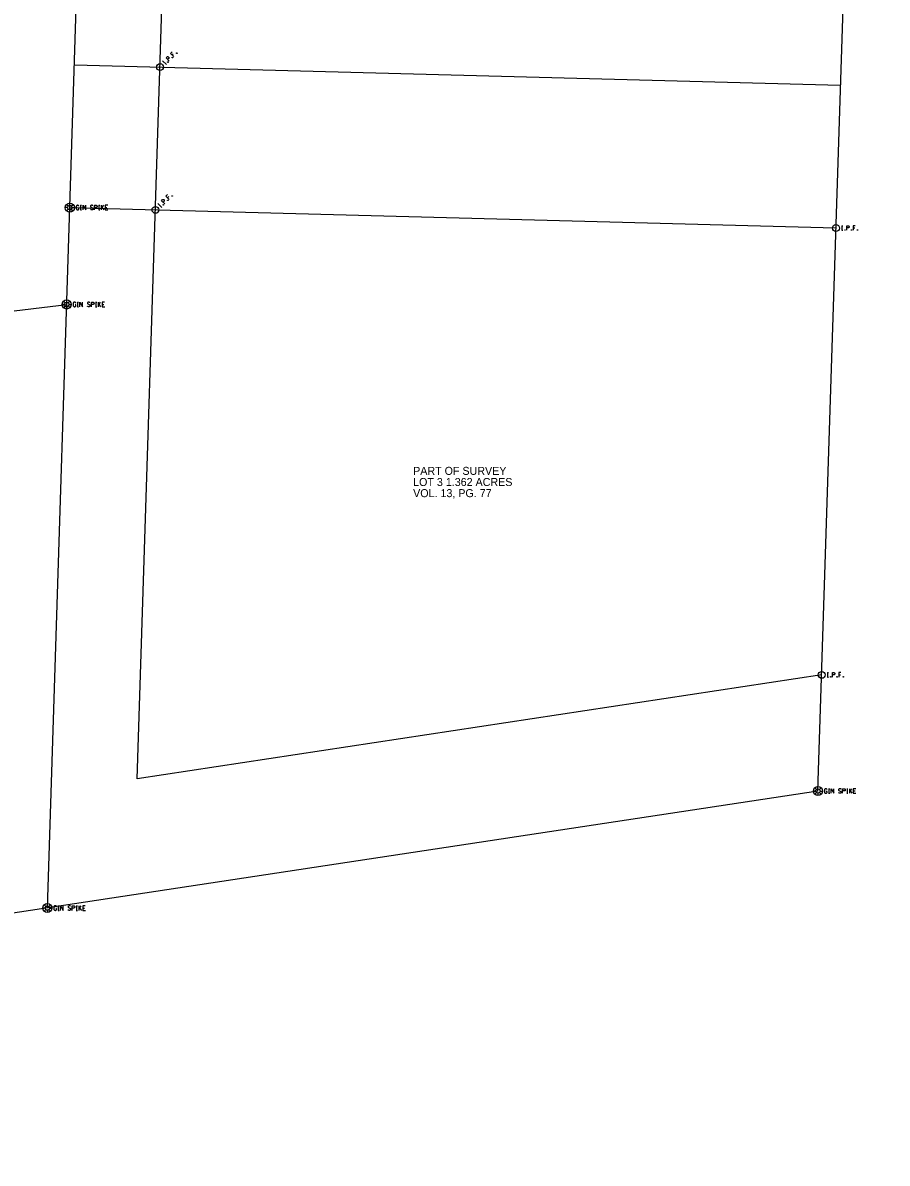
# Model space of a CAD drawing. Extents: x 1532954 to 1577849, y 698998 to 706606.
# Drawn here: x 1534496 to 1534798.6, y 703091.1 to 703490.2 of the extents above; entities that cross this region are included whole.
import ezdxf

# ---------------------------------------------------------------- set-up
doc = ezdxf.new("R2010")
doc.units = 0
doc.layers.add('SC_Scratch3', color=7, linetype='Continuous')

msp = doc.modelspace()

# ---------------------------------------------------------------- linework, layer by layer
at = {"layer": 'SC_Scratch3'}
for p, q in [((1534774.37, 703221.39), (1534798.62, 703978.77)), ((1534504.63, 703180.43), (1534518.99, 703629.17)), ((1534536.09, 703225.67), (1534548.98, 703628.3)), ((1534514.07, 703475.55), (1534782.28, 703468.41)), ((1534511.72, 703425.57), (1534510.87, 703425.57)), ((1534511.94, 703426.1), (1534511.34, 703426.71)), ((1534511.94, 703425.04), (1534511.34, 703424.44)), ((1534512.47, 703426.32), (1534512.47, 703427.17)), ((1534512.47, 703425.57), (1534780.69, 703418.44)), ((1534512.47, 703424.82), (1534512.47, 703423.97)), ((1534513, 703426.1), (1534513.61, 703426.71)), ((1534513, 703425.04), (1534513.61, 703424.44)), ((1534513.22, 703425.57), (1534514.07, 703425.57)), ((1534142.49, 703347.63), (1534511.39, 703391.68)), ((1534510.64, 703391.68), (1534509.79, 703391.68)), ((1534510.86, 703392.21), (1534510.26, 703392.81)), ((1534511.39, 703392.43), (1534511.39, 703393.28)), ((1534511.92, 703392.21), (1534512.52, 703392.81)), ((1534512.14, 703391.68), (1534512.99, 703391.68)), ((1534510.86, 703391.15), (1534510.26, 703390.55)), ((1534511.39, 703390.93), (1534511.39, 703390.08)), ((1534511.92, 703391.15), (1534512.52, 703390.55)), ((1534775.68, 703262.05), (1534536.09, 703225.67)), ((1534774.37, 703221.39), (1533916.61, 703091.14)), ((1534773.62, 703221.39), (1534772.77, 703221.39)), ((1534773.84, 703221.92), (1534773.24, 703222.52)), ((1534773.84, 703220.86), (1534773.24, 703220.26)), ((1534774.37, 703222.14), (1534774.37, 703222.99)), ((1534774.37, 703220.64), (1534774.37, 703219.79)), ((1534774.91, 703221.92), (1534775.51, 703222.52)), ((1534774.91, 703220.86), (1534775.51, 703220.26)), ((1534775.12, 703221.39), (1534775.97, 703221.39)), ((1534503.88, 703180.43), (1534503.03, 703180.43)), ((1534504.1, 703180.96), (1534503.5, 703181.56)), ((1534504.63, 703181.18), (1534504.63, 703182.03)), ((1534505.16, 703180.96), (1534505.76, 703181.56)), ((1534505.38, 703180.43), (1534506.23, 703180.43)), ((1534504.1, 703179.9), (1534503.5, 703179.3)), ((1534504.63, 703179.68), (1534504.63, 703178.83)), ((1534505.16, 703179.9), (1534505.76, 703179.3))]:
    msp.add_line(p, q, dxfattribs=at)
for points in [[(1534548.28, 703480.1), (1534547.74, 703479.56), (1534548.87, 703478.43)], [(1534549.81, 703479.67), (1534549.85, 703479.71), (1534549.89, 703479.72), (1534549.95, 703479.71), (1534550, 703479.66), (1534550.01, 703479.6), (1534550, 703479.56), (1534549.97, 703479.52), (1534549.92, 703479.52), (1534549.87, 703479.53), (1534549.82, 703479.57), (1534549.81, 703479.63), (1534549.81, 703479.67)], [(1534544.92, 703476.74), (1534545.17, 703476.99)], [(1534546.18, 703475.73), (1534545.05, 703476.87)], [(1534546.05, 703475.61), (1534546.3, 703475.86)], [(1534547.28, 703476.84), (1534546.15, 703477.97), (1534546.53, 703478.35), (1534546.58, 703478.38), (1534546.65, 703478.41), (1534546.69, 703478.42), (1534546.73, 703478.42), (1534546.81, 703478.41), (1534546.87, 703478.39), (1534546.96, 703478.33), (1534547.07, 703478.23), (1534547.1, 703478.18), (1534547.13, 703478.11), (1534547.16, 703478.02), (1534547.16, 703477.96), (1534547.15, 703477.92), (1534547.13, 703477.87), (1534547.08, 703477.79), (1534546.71, 703477.42)], [(1534546.7, 703476.56), (1534546.74, 703476.6), (1534546.78, 703476.61), (1534546.84, 703476.6), (1534546.89, 703476.55), (1534546.9, 703476.49), (1534546.9, 703476.45), (1534546.86, 703476.41), (1534546.81, 703476.41), (1534546.76, 703476.42), (1534546.71, 703476.46), (1534546.7, 703476.52), (1534546.7, 703476.56)], [(1534548.29, 703478.15), (1534548.33, 703478.19), (1534548.37, 703478.2), (1534548.43, 703478.19), (1534548.48, 703478.14), (1534548.49, 703478.08), (1534548.49, 703478.04), (1534548.45, 703478), (1534548.4, 703478), (1534548.35, 703478.01), (1534548.3, 703478.05), (1534548.29, 703478.11), (1534548.29, 703478.15)], [(1534548.3, 703479.01), (1534548.68, 703479.39)], [(1534545.69, 703426.87), (1534544.55, 703428), (1534544.93, 703428.37), (1534544.98, 703428.4), (1534545.05, 703428.44), (1534545.09, 703428.44), (1534545.13, 703428.45), (1534545.21, 703428.44), (1534545.27, 703428.41), (1534545.36, 703428.36), (1534545.47, 703428.25), (1534545.5, 703428.21), (1534545.53, 703428.14), (1534545.56, 703428.05), (1534545.56, 703427.99), (1534545.55, 703427.95), (1534545.53, 703427.89), (1534545.48, 703427.82), (1534545.11, 703427.45)], [(1534546.68, 703430.13), (1534546.14, 703429.59), (1534547.28, 703428.46)], [(1534546.7, 703428.18), (1534546.73, 703428.22), (1534546.78, 703428.22), (1534546.83, 703428.21), (1534546.88, 703428.17), (1534546.89, 703428.11), (1534546.89, 703428.07), (1534546.85, 703428.03), (1534546.81, 703428.02), (1534546.75, 703428.03), (1534546.7, 703428.08), (1534546.69, 703428.14), (1534546.7, 703428.18)], [(1534546.7, 703429.04), (1534547.08, 703429.42)], [(1534548.21, 703429.7), (1534548.25, 703429.74), (1534548.3, 703429.74), (1534548.35, 703429.73), (1534548.4, 703429.69), (1534548.41, 703429.63), (1534548.41, 703429.59), (1534548.37, 703429.55), (1534548.33, 703429.54), (1534548.27, 703429.55), (1534548.22, 703429.6), (1534548.21, 703429.66), (1534548.21, 703429.7)], [(1534515.66, 703426.06), (1534515.65, 703426.12), (1534515.61, 703426.18), (1534515.55, 703426.25), (1534515.46, 703426.32), (1534515.4, 703426.35), (1534515.35, 703426.36), (1534515.27, 703426.37), (1534515.12, 703426.37), (1534515.06, 703426.36), (1534515.02, 703426.35), (1534514.97, 703426.32), (1534514.87, 703426.25), (1534514.8, 703426.16), (1534514.77, 703426.06), (1534514.74, 703425.92), (1534514.72, 703425.72), (1534514.72, 703425.45), (1534514.73, 703425.24), (1534514.78, 703425.08), (1534514.86, 703424.92), (1534514.92, 703424.87), (1534514.99, 703424.82), (1534515.13, 703424.77), (1534515.27, 703424.77), (1534515.41, 703424.8), (1534515.46, 703424.82), (1534515.51, 703424.85), (1534515.56, 703424.9), (1534515.61, 703424.98), (1534515.66, 703425.09), (1534515.66, 703425.4), (1534515.4, 703425.4)], [(1534516.19, 703426.37), (1534516.59, 703426.37)], [(1534516.19, 703424.77), (1534516.59, 703424.77)], [(1534516.39, 703424.77), (1534516.39, 703426.37)], [(1534517.1, 703424.77), (1534517.1, 703426.37), (1534518.04, 703424.77), (1534518.04, 703426.37)], [(1534520.56, 703426.26), (1534520.54, 703426.29), (1534520.5, 703426.31), (1534520.39, 703426.35), (1534520.25, 703426.37), (1534520.15, 703426.37), (1534520.11, 703426.37), (1534519.94, 703426.34), (1534519.81, 703426.26), (1534519.72, 703426.16), (1534519.69, 703426.06), (1534519.69, 703425.98), (1534519.72, 703425.88), (1534519.82, 703425.79), (1534520.51, 703425.42), (1534520.57, 703425.37), (1534520.6, 703425.32), (1534520.62, 703425.24), (1534520.62, 703425.16), (1534520.61, 703425.09), (1534520.6, 703425.04), (1534520.57, 703424.98), (1534520.55, 703424.92), (1534520.52, 703424.89), (1534520.49, 703424.85), (1534520.45, 703424.82), (1534520.4, 703424.8), (1534520.36, 703424.79), (1534520.25, 703424.77), (1534520.07, 703424.77), (1534519.96, 703424.8), (1534519.79, 703424.89), (1534519.69, 703424.96)], [(1534521.1, 703424.77), (1534521.1, 703426.37), (1534521.71, 703426.37), (1534521.77, 703426.36), (1534521.86, 703426.34), (1534521.9, 703426.31), (1534521.93, 703426.29), (1534521.99, 703426.22), (1534522.02, 703426.16), (1534522.05, 703426.06), (1534522.05, 703425.91), (1534522.04, 703425.86), (1534522.01, 703425.78), (1534521.96, 703425.69), (1534521.91, 703425.66), (1534521.87, 703425.63), (1534521.81, 703425.61), (1534521.71, 703425.59), (1534521.1, 703425.59)], [(1534522.59, 703426.37), (1534522.99, 703426.37)], [(1534522.59, 703424.77), (1534522.99, 703424.77)], [(1534522.79, 703424.77), (1534522.79, 703426.37)], [(1534523.5, 703426.37), (1534523.5, 703424.77)], [(1534524.23, 703426.37), (1534523.5, 703425.35)], [(1534523.74, 703425.68), (1534524.35, 703424.77)], [(1534525.73, 703426.37), (1534524.86, 703426.37), (1534524.86, 703424.77), (1534525.79, 703424.77)], [(1534524.86, 703425.58), (1534525.47, 703425.58)], [(1534543.32, 703426.77), (1534543.57, 703427.02)], [(1534544.58, 703425.76), (1534543.45, 703426.89)], [(1534544.45, 703425.63), (1534544.7, 703425.88)], [(1534545.11, 703426.59), (1534545.14, 703426.63), (1534545.19, 703426.63), (1534545.24, 703426.62), (1534545.29, 703426.58), (1534545.3, 703426.52), (1534545.3, 703426.48), (1534545.26, 703426.44), (1534545.22, 703426.43), (1534545.16, 703426.44), (1534545.11, 703426.49), (1534545.1, 703426.55), (1534545.11, 703426.59)], [(1534782.7, 703419.23), (1534783.05, 703419.23)], [(1534782.7, 703417.63), (1534783.05, 703417.63)], [(1534782.87, 703417.63), (1534782.87, 703419.23)], [(1534783.83, 703417.84), (1534783.89, 703417.84), (1534783.92, 703417.82), (1534783.95, 703417.77), (1534783.95, 703417.71), (1534783.92, 703417.66), (1534783.89, 703417.63), (1534783.83, 703417.63), (1534783.8, 703417.66), (1534783.77, 703417.71), (1534783.77, 703417.77), (1534783.8, 703417.82), (1534783.83, 703417.84)], [(1534784.44, 703417.63), (1534784.44, 703419.23), (1534784.97, 703419.23), (1534785.02, 703419.22), (1534785.1, 703419.19), (1534785.13, 703419.17), (1534785.17, 703419.14), (1534785.21, 703419.08), (1534785.24, 703419.02), (1534785.26, 703418.91), (1534785.26, 703418.76), (1534785.25, 703418.71), (1534785.23, 703418.64), (1534785.19, 703418.55), (1534785.14, 703418.51), (1534785.11, 703418.49), (1534785.05, 703418.46), (1534784.97, 703418.45), (1534784.44, 703418.45)], [(1534786.08, 703417.84), (1534786.14, 703417.84), (1534786.17, 703417.82), (1534786.2, 703417.77), (1534786.2, 703417.71), (1534786.17, 703417.66), (1534786.14, 703417.63), (1534786.08, 703417.63), (1534786.05, 703417.66), (1534786.01, 703417.71), (1534786.01, 703417.77), (1534786.05, 703417.82), (1534786.08, 703417.84)], [(1534787.45, 703419.23), (1534786.69, 703419.23), (1534786.69, 703417.63)], [(1534786.69, 703418.45), (1534787.23, 703418.45)], [(1534788.23, 703417.84), (1534788.28, 703417.84), (1534788.32, 703417.82), (1534788.35, 703417.77), (1534788.35, 703417.71), (1534788.32, 703417.66), (1534788.28, 703417.63), (1534788.23, 703417.63), (1534788.2, 703417.66), (1534788.16, 703417.71), (1534788.16, 703417.77), (1534788.2, 703417.82), (1534788.23, 703417.84)], [(1534514.58, 703392.17), (1534514.56, 703392.23), (1534514.53, 703392.29), (1534514.46, 703392.35), (1534514.37, 703392.43), (1534514.31, 703392.46), (1534514.26, 703392.47), (1534514.19, 703392.48), (1534514.03, 703392.48), (1534513.97, 703392.47), (1534513.93, 703392.46), (1534513.88, 703392.43), (1534513.78, 703392.35), (1534513.72, 703392.27), (1534513.68, 703392.17), (1534513.66, 703392.03), (1534513.63, 703391.83), (1534513.63, 703391.56), (1534513.64, 703391.35), (1534513.69, 703391.18), (1534513.77, 703391.03), (1534513.83, 703390.98), (1534513.91, 703390.93), (1534514.05, 703390.88), (1534514.19, 703390.88), (1534514.32, 703390.91), (1534514.37, 703390.93), (1534514.43, 703390.96), (1534514.48, 703391.01), (1534514.53, 703391.08), (1534514.58, 703391.2), (1534514.58, 703391.51), (1534514.31, 703391.51)], [(1534515.11, 703392.48), (1534515.51, 703392.48)], [(1534515.31, 703390.88), (1534515.31, 703392.48)], [(1534516.01, 703390.88), (1534516.01, 703392.48), (1534516.96, 703390.88), (1534516.96, 703392.48)], [(1534519.48, 703392.37), (1534519.45, 703392.39), (1534519.41, 703392.42), (1534519.3, 703392.46), (1534519.16, 703392.48), (1534519.06, 703392.48), (1534519.02, 703392.48), (1534518.86, 703392.44), (1534518.72, 703392.37), (1534518.63, 703392.27), (1534518.61, 703392.17), (1534518.61, 703392.09), (1534518.63, 703391.99), (1534518.73, 703391.9), (1534519.43, 703391.52), (1534519.49, 703391.47), (1534519.51, 703391.42), (1534519.54, 703391.35), (1534519.54, 703391.27), (1534519.53, 703391.2), (1534519.51, 703391.15), (1534519.49, 703391.08), (1534519.46, 703391.03), (1534519.44, 703390.99), (1534519.4, 703390.96), (1534519.36, 703390.93), (1534519.31, 703390.91), (1534519.28, 703390.89), (1534519.16, 703390.88), (1534518.99, 703390.88), (1534518.87, 703390.91), (1534518.71, 703390.99), (1534518.61, 703391.07)], [(1534520.02, 703390.88), (1534520.02, 703392.48), (1534520.62, 703392.48), (1534520.69, 703392.47), (1534520.77, 703392.44), (1534520.81, 703392.42), (1534520.85, 703392.39), (1534520.9, 703392.33), (1534520.94, 703392.27), (1534520.96, 703392.17), (1534520.96, 703392.01), (1534520.95, 703391.96), (1534520.93, 703391.89), (1534520.88, 703391.8), (1534520.82, 703391.76), (1534520.79, 703391.74), (1534520.72, 703391.71), (1534520.62, 703391.7), (1534520.02, 703391.7)], [(1534521.51, 703392.48), (1534521.91, 703392.48)], [(1534521.71, 703390.88), (1534521.71, 703392.48)], [(1534522.41, 703392.48), (1534522.41, 703390.88)], [(1534523.14, 703392.48), (1534522.41, 703391.46)], [(1534522.65, 703391.79), (1534523.27, 703390.88)], [(1534524.64, 703392.48), (1534523.77, 703392.48), (1534523.77, 703390.88), (1534524.7, 703390.88)], [(1534523.77, 703391.69), (1534524.39, 703391.69)], [(1534515.11, 703390.88), (1534515.51, 703390.88)], [(1534521.51, 703390.88), (1534521.91, 703390.88)], [(1534777.69, 703262.85), (1534778.04, 703262.85)], [(1534777.69, 703261.25), (1534778.04, 703261.25)], [(1534777.87, 703261.25), (1534777.87, 703262.85)], [(1534778.83, 703261.46), (1534778.88, 703261.46), (1534778.91, 703261.44), (1534778.95, 703261.39), (1534778.95, 703261.32), (1534778.91, 703261.27), (1534778.88, 703261.25), (1534778.83, 703261.25), (1534778.79, 703261.27), (1534778.76, 703261.32), (1534778.76, 703261.39), (1534778.79, 703261.44), (1534778.83, 703261.46)], [(1534779.43, 703261.25), (1534779.43, 703262.85), (1534779.96, 703262.85), (1534780.02, 703262.83), (1534780.09, 703262.81), (1534780.13, 703262.78), (1534780.16, 703262.76), (1534780.2, 703262.7), (1534780.24, 703262.63), (1534780.26, 703262.53), (1534780.26, 703262.38), (1534780.25, 703262.33), (1534780.23, 703262.25), (1534780.18, 703262.17), (1534780.14, 703262.13), (1534780.1, 703262.1), (1534780.05, 703262.08), (1534779.96, 703262.07), (1534779.43, 703262.07)], [(1534781.07, 703261.46), (1534781.13, 703261.46), (1534781.16, 703261.44), (1534781.2, 703261.39), (1534781.2, 703261.32), (1534781.16, 703261.27), (1534781.13, 703261.25), (1534781.07, 703261.25), (1534781.04, 703261.27), (1534781.01, 703261.32), (1534781.01, 703261.39), (1534781.04, 703261.44), (1534781.07, 703261.46)], [(1534782.44, 703262.85), (1534781.68, 703262.85), (1534781.68, 703261.25)], [(1534781.68, 703262.07), (1534782.22, 703262.07)], [(1534783.22, 703261.46), (1534783.28, 703261.46), (1534783.31, 703261.44), (1534783.35, 703261.39), (1534783.35, 703261.32), (1534783.31, 703261.27), (1534783.28, 703261.25), (1534783.22, 703261.25), (1534783.19, 703261.27), (1534783.16, 703261.32), (1534783.16, 703261.39), (1534783.19, 703261.44), (1534783.22, 703261.46)], [(1534777.56, 703221.88), (1534777.55, 703221.94), (1534777.51, 703222), (1534777.45, 703222.06), (1534777.36, 703222.14), (1534777.3, 703222.17), (1534777.25, 703222.18), (1534777.17, 703222.19), (1534777.02, 703222.19), (1534776.96, 703222.18), (1534776.92, 703222.17), (1534776.87, 703222.14), (1534776.77, 703222.06), (1534776.71, 703221.98), (1534776.67, 703221.88), (1534776.64, 703221.74), (1534776.62, 703221.54), (1534776.62, 703221.27), (1534776.63, 703221.06), (1534776.68, 703220.89), (1534776.76, 703220.74), (1534776.82, 703220.69), (1534776.89, 703220.64), (1534777.03, 703220.59), (1534777.17, 703220.59), (1534777.31, 703220.62), (1534777.36, 703220.64), (1534777.41, 703220.67), (1534777.46, 703220.72), (1534777.51, 703220.79), (1534777.56, 703220.91), (1534777.56, 703221.22), (1534777.3, 703221.22)], [(1534778.09, 703222.19), (1534778.49, 703222.19)], [(1534778.09, 703220.59), (1534778.49, 703220.59)], [(1534778.29, 703220.59), (1534778.29, 703222.19)], [(1534779, 703220.59), (1534779, 703222.19), (1534779.94, 703220.59), (1534779.94, 703222.19)], [(1534782.46, 703222.08), (1534782.44, 703222.1), (1534782.4, 703222.13), (1534782.29, 703222.17), (1534782.15, 703222.19), (1534782.05, 703222.19), (1534782.01, 703222.19), (1534781.85, 703222.15), (1534781.71, 703222.08), (1534781.62, 703221.98), (1534781.59, 703221.88), (1534781.59, 703221.8), (1534781.62, 703221.7), (1534781.72, 703221.61), (1534782.41, 703221.23), (1534782.48, 703221.18), (1534782.5, 703221.13), (1534782.53, 703221.06), (1534782.53, 703220.98), (1534782.51, 703220.91), (1534782.5, 703220.86), (1534782.48, 703220.79), (1534782.45, 703220.74), (1534782.42, 703220.7), (1534782.39, 703220.67), (1534782.35, 703220.64), (1534782.3, 703220.62), (1534782.26, 703220.6), (1534782.15, 703220.59), (1534781.97, 703220.59), (1534781.86, 703220.62), (1534781.69, 703220.7), (1534781.59, 703220.78)], [(1534783, 703220.59), (1534783, 703222.19), (1534783.61, 703222.19), (1534783.67, 703222.18), (1534783.76, 703222.15), (1534783.8, 703222.13), (1534783.84, 703222.1), (1534783.89, 703222.04), (1534783.92, 703221.98), (1534783.95, 703221.88), (1534783.95, 703221.72), (1534783.94, 703221.67), (1534783.91, 703221.6), (1534783.86, 703221.51), (1534783.81, 703221.47), (1534783.77, 703221.45), (1534783.71, 703221.42), (1534783.61, 703221.41), (1534783, 703221.41)], [(1534784.49, 703222.19), (1534784.89, 703222.19)], [(1534784.49, 703220.59), (1534784.89, 703220.59)], [(1534784.69, 703220.59), (1534784.69, 703222.19)], [(1534785.4, 703222.19), (1534785.4, 703220.59)], [(1534786.13, 703222.19), (1534785.4, 703221.17)], [(1534785.64, 703221.5), (1534786.25, 703220.59)], [(1534787.63, 703222.19), (1534786.76, 703222.19), (1534786.76, 703220.59), (1534787.69, 703220.59)], [(1534786.76, 703221.4), (1534787.38, 703221.4)], [(1534507.81, 703180.91), (1534507.8, 703180.98), (1534507.76, 703181.04), (1534507.7, 703181.1), (1534507.61, 703181.18), (1534507.55, 703181.2), (1534507.5, 703181.22), (1534507.42, 703181.23), (1534507.27, 703181.23), (1534507.21, 703181.22), (1534507.17, 703181.2), (1534507.12, 703181.18), (1534507.02, 703181.1), (1534506.96, 703181.02), (1534506.92, 703180.91), (1534506.9, 703180.78), (1534506.87, 703180.57), (1534506.87, 703180.31), (1534506.88, 703180.1), (1534506.93, 703179.93), (1534507.01, 703179.78), (1534507.07, 703179.73), (1534507.15, 703179.68), (1534507.29, 703179.63), (1534507.42, 703179.63), (1534507.56, 703179.65), (1534507.61, 703179.68), (1534507.66, 703179.7), (1534507.71, 703179.76), (1534507.76, 703179.83), (1534507.81, 703179.94), (1534507.81, 703180.26), (1534507.55, 703180.26)], [(1534508.34, 703181.23), (1534508.75, 703181.23)], [(1534508.55, 703179.63), (1534508.55, 703181.23)], [(1534509.25, 703179.63), (1534509.25, 703181.23), (1534510.2, 703179.63), (1534510.2, 703181.23)], [(1534512.71, 703181.12), (1534512.69, 703181.14), (1534512.65, 703181.17), (1534512.54, 703181.2), (1534512.4, 703181.23), (1534512.3, 703181.23), (1534512.26, 703181.23), (1534512.1, 703181.19), (1534511.96, 703181.12), (1534511.87, 703181.02), (1534511.85, 703180.91), (1534511.85, 703180.84), (1534511.87, 703180.74), (1534511.97, 703180.65), (1534512.66, 703180.27), (1534512.73, 703180.22), (1534512.75, 703180.17), (1534512.78, 703180.1), (1534512.78, 703180.02), (1534512.77, 703179.94), (1534512.75, 703179.89), (1534512.73, 703179.83), (1534512.7, 703179.78), (1534512.68, 703179.74), (1534512.64, 703179.7), (1534512.6, 703179.68), (1534512.55, 703179.65), (1534512.51, 703179.64), (1534512.4, 703179.63), (1534512.22, 703179.63), (1534512.11, 703179.65), (1534511.95, 703179.74), (1534511.85, 703179.82)], [(1534513.26, 703179.63), (1534513.26, 703181.23), (1534513.86, 703181.23), (1534513.92, 703181.22), (1534514.01, 703181.19), (1534514.05, 703181.17), (1534514.09, 703181.14), (1534514.14, 703181.08), (1534514.18, 703181.02), (1534514.2, 703180.91), (1534514.2, 703180.76), (1534514.19, 703180.71), (1534514.16, 703180.64), (1534514.11, 703180.55), (1534514.06, 703180.51), (1534514.03, 703180.49), (1534513.96, 703180.46), (1534513.86, 703180.45), (1534513.26, 703180.45)], [(1534514.74, 703181.23), (1534515.15, 703181.23)], [(1534514.94, 703179.63), (1534514.94, 703181.23)], [(1534515.65, 703181.23), (1534515.65, 703179.63)], [(1534516.38, 703181.23), (1534515.65, 703180.21)], [(1534515.89, 703180.54), (1534516.51, 703179.63)], [(1534517.88, 703181.23), (1534517.01, 703181.23), (1534517.01, 703179.63), (1534517.94, 703179.63)], [(1534517.01, 703180.44), (1534517.63, 703180.44)], [(1534508.34, 703179.63), (1534508.75, 703179.63)], [(1534514.74, 703179.63), (1534515.15, 703179.63)]]:
    msp.add_lwpolyline(points, dxfattribs=at)
for centre, radius in [((1534544.06, 703474.75), 1.2), ((1534512.47, 703425.57), 1.6), ((1534512.47, 703425.57), 0.75), ((1534542.46, 703424.78), 1.2), ((1534780.68, 703418.43), 1.2), ((1534511.39, 703391.68), 1.6), ((1534511.39, 703391.68), 0.75), ((1534775.68, 703262.05), 1.2), ((1534774.37, 703221.39), 1.6), ((1534774.37, 703221.39), 0.75), ((1534504.63, 703180.43), 1.6), ((1534504.63, 703180.43), 0.75)]:
    msp.add_circle(centre, radius, dxfattribs=at)

# ---------------------------------------------------------------- texts
for s, p in [('PART OF SURVEY', (1534632.66, 703332.04)), ('LOT 3 1.362 ACRES', (1534632.66, 703328.14)), ('VOL. 13, PG. 77', (1534632.66, 703324.24))]:
    msp.add_text(s, height=2.8, dxfattribs=at).set_placement(p)

doc.saveas('drawing.dxf')
